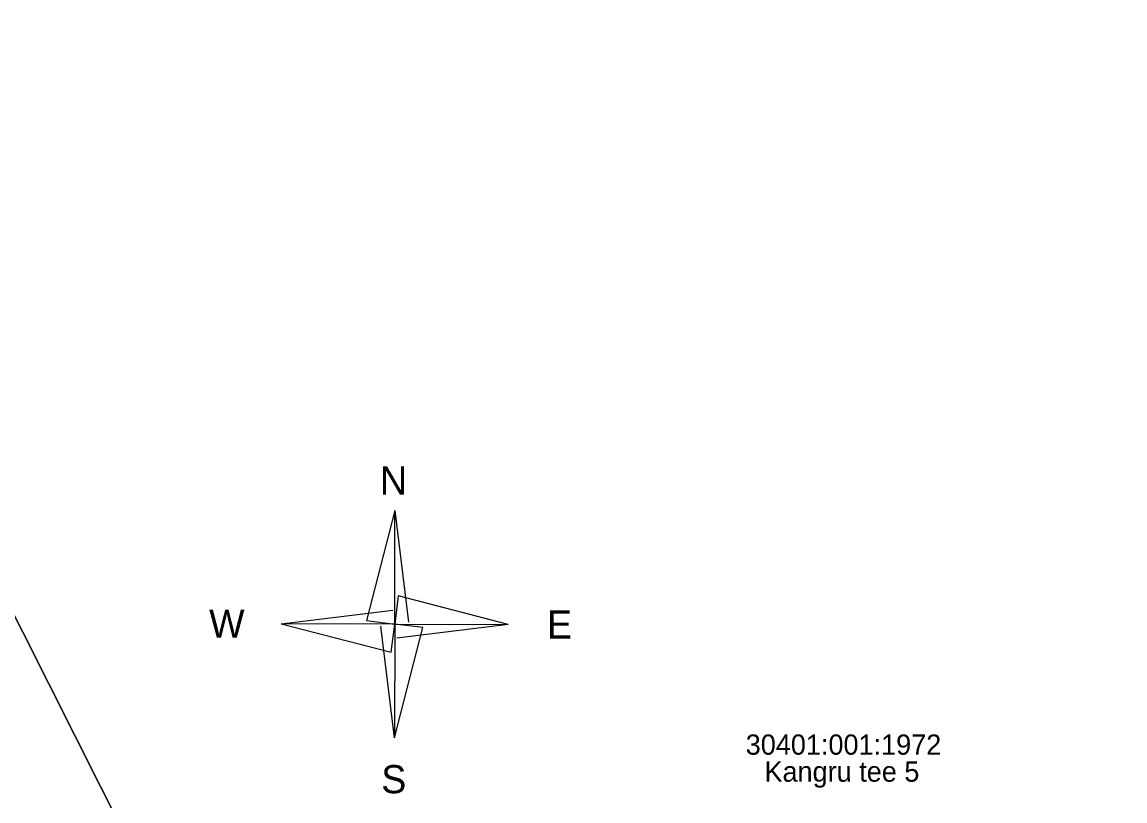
# Model space of a CAD drawing. Extents: x 543497 to 552146, y 6567125 to 6579845.
# Drawn here: x 546345.61 to 546394.68, y 6577813.08 to 6577847.71 of the extents above; entities that cross this region are included whole.
import ezdxf

# ---------------------------------------------------------------- set-up
doc = ezdxf.new("R2010")
doc.units = 0
doc.layers.add('xref_Kangru tee 1_geodeesia$0$PIIR', color=7, linetype='Continuous')
doc.layers.add('xref_Kangru tee 1_geodeesia$0$VORMISTUS', color=7, linetype='Continuous')

# ---------------------------------------------------------------- blocks, each defined once
blk = doc.blocks.new('xref_Kangru tee 1_geodeesia$0$reinord')
for p, q in [((0.012, 5.052), (0.619, 0.089)), ((-5.052, 0.012), (-0.089, 0.619)), ((-0.012, -5.052), (-0.619, -0.089)), ((5.052, -0.012), (0.089, -0.619))]:
    blk.add_line(p, q)
for points in [[(0.012, 5.052), (-1.25, 0.159), (0, 0)], [(5.052, -0.012), (0.159, 1.25), (0, 0)], [(-5.052, 0.012), (-0.159, -1.25), (0, 0)], [(-0.012, -5.052), (1.25, -0.159), (0, 0)]]:
    blk.add_lwpolyline(points, close=True)
for s, p in [('N', (-0.657, 5.761)), ('W', (-8.259, -0.608)), ('E', (6.776, -0.642)), ('S', (-0.598, -7.52))]:
    blk.add_text(s, height=1.25).set_placement(p)

msp = doc.modelspace()

# ---------------------------------------------------------------- linework, layer by layer
at = {"layer": 'xref_Kangru tee 1_geodeesia$0$PIIR'}
for points in [[(546343.49, 6577782.42), (546113.86, 6577718.6), (546110.26, 6577728.46), (546099.69, 6577747.34), (546096.86, 6577764.18), (546081.11, 6577806.12), (546028.71, 6577946.4), (546181.64, 6578015.13), (546193.98, 6577986.84), (546253.63, 6577898.8), (546194.56, 6577846.11), (546236.46, 6577818.84), (546280.11, 6577843.57), (546324.91, 6577861.74), (546356.01, 6577800), (546343.49, 6577782.42)], [(546343.49, 6577782.42), (546356.01, 6577800), (546324.91, 6577861.74), (546309.3, 6577910.03), (546301.14, 6577913.42), (546353.06, 6577980.64), (546439.17, 6577910.04), (546385.17, 6577868.1), (546425.19, 6577804.45), (546343.49, 6577782.42)]]:
    msp.add_lwpolyline(points, dxfattribs=at)

# ---------------------------------------------------------------- block references
at = {"layer": 'xref_Kangru tee 1_geodeesia$0$VORMISTUS'}
msp.add_blockref('xref_Kangru tee 1_geodeesia$0$reinord', (546362.195, 6577820.946), dxfattribs=at)

# ---------------------------------------------------------------- texts
at = {"layer": 'xref_Kangru tee 1_geodeesia$0$PIIR'}
for s, p in [('30401:001:1972', (546377.812, 6577815.139)), ('Kangru tee 5', (546378.647, 6577813.939))]:
    msp.add_text(s, height=0.9, dxfattribs=at).set_placement(p)

doc.saveas('drawing.dxf')
